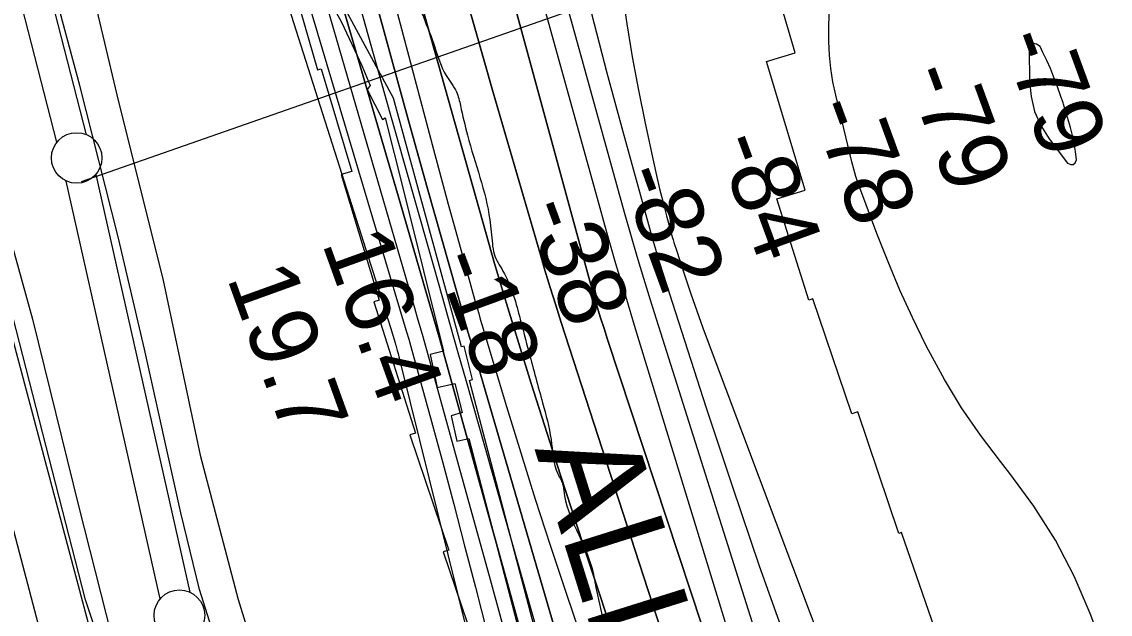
# Model space of a CAD drawing. Extents: x 3405885 to 3443815, y 558517 to 583997.
# Drawn here: x 3413539 to 3414615, y 576541 to 577127 of the extents above; entities that cross this region are included whole.
import ezdxf

# ---------------------------------------------------------------- set-up
doc = ezdxf.new("R2010")
doc.units = 0
for name, color, linetype in [('V-CHAN-DOCK', 7, 'Continuous'), ('V-FLOD-BASE', 7, 'Continuous'), ('V-LEVE-TOET', 7, 'Continuous'), ('V-RIVR-EDGE', 7, 'Continuous'), ('V-RIVR-RANG', 7, 'Continuous'), ('V-ROAD-CNTR', 7, 'Continuous'), ('V-RRAP-RVMT', 7, 'Continuous'), ('V-RRAP-RVMT-IDEN', 7, 'Continuous'), ('V-SURV-LINE', 7, 'Continuous'), ('V-TOPO-DPTH', 7, 'Continuous'), ('V-TOPO-MAJR', 7, 'Continuous'), ('V-TOPO-MINR', 7, 'Continuous'), ('V-TOPO-SHOR', 7, 'Continuous'), ('V-TOPO-WATR', 7, 'Continuous')]:
    doc.layers.add(name, color=color, linetype=linetype)

msp = doc.modelspace()

# ---------------------------------------------------------------- linework, layer by layer
at = {"layer": 'V-CHAN-DOCK'}
for points in [[(3414098.9, 576327.5), (3413981.9, 576772.3), (3413984.8, 576773), (3413976.8, 576806), (3413974, 576805.3), (3413906.9, 577051.1), (3413848.5, 577159.2), (3413854, 577160.6), (3413844.4, 577189.7), (3413841.9, 577189), (3413800.6, 577346.9), (3413804.2, 577347.4), (3413685.9, 577792.6)], [(3413838.8, 577156.7), (3413855.3, 577126.4), (3413875.6, 577083.4), (3413883.9, 577063.6), (3413880.8, 577059.8), (3413896, 577030.1), (3413898.5, 577031.6), (3413916.7, 576960), (3413956.3, 576801.1), (3413943, 576798), (3413949.9, 576765.4), (3413967.5, 576769.2), (3413974.8, 576740.5), (3413963.7, 576737.1), (3413969.5, 576712.1), (3413981.3, 576714.8), (3414038.7, 576494.8)]]:
    msp.add_lwpolyline(points, dxfattribs=at)
at = {"layer": 'V-FLOD-BASE'}
msp.add_lwpolyline([(3413966.8, 575593.2), (3413930, 575533.2), (3413867.4, 575424.5), (3413866.3, 575435.7), (3413891.6, 575528.1), (3413926.7, 575661.7), (3413958.1, 575773.5), (3413962.9, 575792.9), (3413964.2, 575799.4), (3413964.2, 575804.7), (3413956.2, 575840.2), (3413920.9, 575949.5), (3413875.3, 576086.5), (3413833.1, 576215.9), (3413788.5, 576347.1), (3413730.7, 576515.5), (3413715.1, 576565.7), (3413696.7, 576641.3), (3413660.7, 576803.1), (3413634.6, 576914.3), (3413596.7, 577063.8), (3413554.1, 577222), (3413512.2, 577391.5)], dxfattribs=at)
at = {"layer": 'V-LEVE-TOET'}
for points in [[(3413499, 577627.3), (3413496.6, 577619.1), (3413497.1, 577610.8), (3413502.2, 577577.8), (3413521.1, 577498.1), (3413563.2, 577351), (3413591.9, 577229.9), (3413633.2, 577054.6), (3413679.1, 576870.9), (3413715.7, 576698.5), (3413753.1, 576555.6), (3413784.9, 576453.4), (3413834.6, 576306.2), (3413880.9, 576173.3), (3413933, 576029.7), (3413974, 575893.8), (3413991.8, 575823.5), (3413994.1, 575811.1), (3413994, 575804.1), (3413975.8, 575718.7), (3413949.8, 575619.2)], [(3413389.6, 577437), (3413421.5, 577317.7), (3413459.4, 577170.7), (3413495.1, 577029.5), (3413549.8, 576832.8), (3413595.7, 576646.8), (3413644.6, 576454.9), (3413682.6, 576319.6), (3413700.5, 576256.6)]]:
    msp.add_lwpolyline(points, dxfattribs=at)
at = {"layer": 'V-RIVR-EDGE'}
msp.add_spline([(3412820.9, 582098.3), (3412817.8, 582058), (3412815.6, 582029.5), (3412817.7, 582007.9), (3412825.7, 581980.1), (3412850.3, 581879.9), (3412863.7, 581832.7), (3412872, 581799.1), (3412892.3, 581722.3), (3412903.2, 581678.4), (3412909.6, 581634.8), (3412920.5, 581599), (3412934, 581569.3), (3412943.4, 581548.5), (3412954.7, 581511.2), (3412955.3, 581484.9), (3412959.7, 581464), (3412965.1, 581459.6), (3412977.9, 581445), (3412992.4, 581409.1), (3413006.5, 581353.1), (3413015.2, 581302.3), (3413018.7, 581260.3), (3413013.9, 581236.1), (3413008.8, 581220.1), (3413005.1, 581206.5), (3413003.6, 581194.5), (3413004.7, 581180.2), (3413009.3, 581149.1), (3413020.6, 581117.3), (3413042, 581073), (3413073, 581031.3), (3413081, 581018.1), (3413088.7, 580999.8), (3413094.4, 580977.9), (3413100.2, 580939.1), (3413102.7, 580912), (3413106.3, 580894.1), (3413113.5, 580861.9), (3413124.8, 580824.3), (3413140, 580781.4), (3413146.5, 580756.9), (3413148.7, 580740.1), (3413153.8, 580721.8), (3413161, 580692.6), (3413184.2, 580615.7), (3413194, 580582.5), (3413204.2, 580568.2), (3413207.8, 580561.6), (3413214, 580535.3), (3413232.1, 580461.7), (3413244, 580397.7), (3413253, 580345.1), (3413251.9, 580330.8), (3413256.4, 580258.4), (3413262.5, 580217.5), (3413264.6, 580175.4), (3413271.5, 580146.5), (3413278.7, 580117.3), (3413280.2, 580104.8), (3413276.4, 580060.6), (3413276.3, 580025.9), (3413275.6, 580012.4), (3413275.5, 580006.1), (3413277.7, 580003.2), (3413288, 580000.6), (3413298.6, 579998.4), (3413303.7, 579992.2), (3413305.5, 579985.2), (3413310.1, 579953.8), (3413314.5, 579931.1), (3413321, 579914.6), (3413327.2, 579894.5), (3413327.1, 579868.9), (3413323.4, 579842.6), (3413317.9, 579835.3), (3413316, 579824.7), (3413315.6, 579806.5), (3413320, 579780.1), (3413328, 579765.1), (3413335.6, 579758.2), (3413338.2, 579753.4), (3413338.9, 579747.5), (3413338.9, 579742.8), (3413335.5, 579730.7), (3413330.8, 579723.1), (3413327.8, 579714.3), (3413325.2, 579701.2), (3413326.7, 579689.5), (3413332.1, 579675.9), (3413338.3, 579668.2), (3413342.7, 579666.4), (3413352.6, 579666.7), (3413357.3, 579663.4), (3413365.3, 579652.4), (3413371.9, 579635.2), (3413374.8, 579618.4), (3413377.6, 579592.5), (3413379.4, 579557.4), (3413373.8, 579521.6), (3413375.2, 579501.1), (3413382.1, 579476.9), (3413395.1, 579440), (3413408.6, 579400.8), (3413417.6, 579358.8), (3413445.2, 579297.7), (3413449.9, 579271.7), (3413449.8, 579233.3), (3413439.5, 579191.3), (3413438.7, 579182.2), (3413439.8, 579172.7), (3413446, 579161.7), (3413464.9, 579134.6), (3413487.5, 579101.6), (3413497, 579074.9), (3413502.7, 579046.4), (3413506.7, 579018.2), (3413510.6, 578990.8), (3413518.6, 578952.4), (3413529.8, 578903.8), (3413538.1, 578871.6), (3413547.9, 578834.6), (3413558.4, 578787.4), (3413566.7, 578743.2), (3413574.6, 578699.3), (3413585.1, 578637.1), (3413595.2, 578577.2), (3413599.5, 578547.5), (3413610.7, 578516.1), (3413620.2, 578504), (3413626, 578499.2), (3413635.5, 578497), (3413635.9, 578494.4), (3413634.1, 578490.1), (3413632.2, 578487.1), (3413632.2, 578479.5), (3413633.2, 578455), (3413642.2, 578391), (3413644.3, 578359.2), (3413649, 578338.7), (3413656.3, 578322.2), (3413667.6, 578313.8), (3413676, 578309), (3413684.4, 578305.3), (3413688.8, 578300.2), (3413697.9, 578288.5), (3413702.2, 578272.4), (3413709.1, 578250.8), (3413714.9, 578233.2), (3413728.7, 578187.2), (3413734.8, 578151.3), (3413738.8, 578114.4), (3413740.5, 578084), (3413746.7, 578059.2), (3413750.7, 578043.4), (3413751.3, 578020), (3413747.6, 577990.8), (3413742, 577955), (3413736.9, 577934.5), (3413735.4, 577919.6), (3413733.5, 577904.2), (3413737.1, 577880.1), (3413741.4, 577864.7), (3413741.4, 577863.2), (3413750.2, 577865.8), (3413755, 577862.8), (3413760, 577845.7), (3413773.8, 577798.1), (3413781.8, 577765.2), (3413793, 577724.9), (3413797, 577700.4), (3413803.4, 577637.2), (3413804.4, 577613.8), (3413807.7, 577591.8), (3413815.3, 577561.1), (3413829.4, 577524.9), (3413841.8, 577493.8), (3413853.8, 577466), (3413863.2, 577445.5), (3413869.8, 577431.2), (3413869.8, 577426.1), (3413869.7, 577412.9), (3413868.9, 577389.5), (3413869.2, 577353), (3413871, 577339.8), (3413873.9, 577328.5), (3413883, 577306.5), (3413889.5, 577287.9), (3413905.1, 577244.3), (3413913.5, 577211), (3413925.4, 577161.3), (3413947.6, 577101.7), (3413958.8, 577073.5), (3413969, 577057.4), (3413973, 577043.8), (3413979.9, 577014.6), (3414002, 576930.8), (3414004.5, 576907.4), (3414006.3, 576897.2), (3414015, 576880.3), (3414024.5, 576858.8), (3414031.3, 576835.7), (3414040.8, 576799.5), (3414054.2, 576750.1), (3414062.5, 576713.9), (3414069.3, 576679.9), (3414074.4, 576668.5), (3414075.1, 576663.4), (3414103.1, 576586.2), (3414107.4, 576564.6), (3414115.4, 576529.2), (3414119, 576508), (3414142.2, 576433.7), (3414153.5, 576399.3), (3414159.6, 576378.5), (3414164.7, 576348.8), (3414174.1, 576303.8), (3414178, 576275), (3414184.1, 576248.3), (3414191.1, 576234), (3414204.1, 576202.1), (3414212.1, 576179.5), (3414243, 576089.5), (3414264.8, 576025.4), (3414269.5, 576005.7), (3414269.4, 575994.4), (3414267.6, 575989.1)], degree=3, dxfattribs=at)
at = {"layer": 'V-RIVR-RANG'}
msp.add_line((3413598.5, 576968.9), (3414485.8, 577279.2), dxfattribs=at)
at = {"layer": 'V-ROAD-CNTR'}
msp.add_lwpolyline([(3412427.1, 581014.8), (3412474.8, 580838.1), (3412987, 578854.7), (3413723.7, 576086.7)], dxfattribs=at)
at = {"layer": 'V-RRAP-RVMT'}
for points in [[(3414453.7, 576492.6), (3414409.1, 576621.8), (3414406.4, 576620.8), (3414365.7, 576741.2), (3414359.7, 576739.2), (3414321.2, 576853), (3414317.2, 576851.7), (3414285.6, 576951.7), (3414313.7, 576960.2), (3414275.4, 577087.5), (3414304, 577096), (3414271.4, 577206.1), (3414281.9, 577209.2), (3414243, 577344.3), (3414262.9, 577350.2), (3414224.5, 577479.4), (3414222.9, 577478.9), (3414188.7, 577597.3), (3414195.6, 577599.4), (3414154.2, 577736.4)], [(3413652.8, 577721.4), (3413690, 577595.9), (3413688.2, 577595.4), (3413725.6, 577471.8), (3413722.8, 577471), (3413763.6, 577330.1), (3413764, 577330.2), (3413793.3, 577231.6), (3413788.3, 577230.2), (3413831.8, 577079.3), (3413835.3, 577080.3), (3413865.5, 576978.7), (3413855.2, 576975.6), (3413892.6, 576851.5), (3413887.4, 576849.9), (3413928.5, 576720.2), (3413923, 576718.4), (3413961.4, 576604.5), (3413956, 576602.7), (3413997.6, 576479.5)]]:
    msp.add_lwpolyline(points, dxfattribs=at)
at = {"layer": 'V-SURV-LINE'}
for points in [[(3413574.1, 577007.7), (3412835.6, 579881.8)], [(3412864.6, 579889.2), (3413603.1, 577015.1)], [(3413612.6, 576975.9), (3413705.5, 576562.9)], [(3413676.2, 576556.3), (3413583.3, 576969.3)]]:
    msp.add_lwpolyline(points, dxfattribs=at)
for centre in [(3413593.6, 576992.1), (3413695.2, 576540.1)]:
    msp.add_circle(centre, 25, dxfattribs=at)
at = {"layer": 'V-TOPO-DPTH'}
for points in [[(3413870.4, 577720.3), (3413910.7, 577570.7), (3413931, 577495.3), (3413951.4, 577420), (3413971.8, 577344.6), (3413992.3, 577269.3), (3414092.8, 576899.2), (3414095.8, 576888.3), (3414098.8, 576877.5), (3414101.9, 576866.6), (3414105, 576855.8), (3414108.2, 576844.9), (3414111.5, 576834.2), (3414114.9, 576823.4), (3414118.4, 576812.7), (3414340.3, 576140.2), (3414345.1, 576125.9), (3414350, 576111.6), (3414355.1, 576097.4), (3414360.2, 576083.2), (3414623.5, 575371.4)], [(3413870.4, 577720.3), (3413910.7, 577570.7), (3413931, 577495.3), (3413951.4, 577420), (3413971.8, 577344.6), (3413992.3, 577269.3), (3414092.8, 576899.2), (3414095.8, 576888.3), (3414098.8, 576877.5), (3414101.9, 576866.6), (3414105, 576855.8), (3414108.2, 576844.9), (3414111.5, 576834.2), (3414114.9, 576823.4), (3414118.4, 576812.7), (3414340.3, 576140.2), (3414345.1, 576125.9), (3414350, 576111.6), (3414355.1, 576097.4), (3414360.2, 576083.2), (3414623.5, 575371.4)], [(3414176.3, 576509.8), (3414149.5, 576591.8), (3414072.6, 576829.5), (3414067.2, 576846.7), (3414061.8, 576864), (3414056.5, 576881.3), (3414051.4, 576898.6), (3414005.4, 577056.7), (3413978, 577153.3), (3413951.2, 577250), (3413925.5, 577347), (3413900.6, 577444.3), (3413843.2, 577673.7)], [(3414176.3, 576509.8), (3414149.5, 576591.8), (3414072.6, 576829.5), (3414067.2, 576846.7), (3414061.8, 576864), (3414056.5, 576881.3), (3414051.4, 576898.6), (3414005.4, 577056.7), (3413978, 577153.3), (3413951.2, 577250), (3413925.5, 577347), (3413900.6, 577444.3), (3413843.2, 577673.7)], [(3413754, 577659.2), (3413869.2, 577223.1), (3413886.5, 577157.9), (3413904.1, 577092.8), (3413922, 577027.8), (3413940.2, 576962.9), (3413969.6, 576858.5), (3413973.2, 576845.8), (3413976.8, 576833.1), (3413980.4, 576820.4), (3413984.1, 576807.7), (3414083.7, 576466.7)], [(3414083.7, 576466.7), (3413984.1, 576807.7), (3413980.4, 576820.4), (3413976.8, 576833.1), (3413973.2, 576845.8), (3413969.6, 576858.5), (3413940.2, 576962.9), (3413922, 577027.8), (3413904.1, 577092.8), (3413886.5, 577157.9), (3413869.2, 577223.1), (3413754, 577659.2)], [(3413669.5, 577652.8), (3413721.3, 577482.2), (3413749, 577390.6), (3413776.6, 577299), (3413804.2, 577207.3), (3413831.6, 577115.6), (3413917.5, 576827.7), (3413919.7, 576820.4), (3413921.8, 576813.1), (3413923.9, 576805.8), (3413925.9, 576798.4), (3413944.3, 576731.5), (3413955.5, 576690.7), (3413966.4, 576649.8), (3413977.1, 576608.8), (3413987.7, 576567.8), (3414103.6, 576111.6)], [(3413718.9, 577631.5), (3413770.4, 577445.8), (3413839.6, 577200.4), (3413913, 576949), (3413952.7, 576812.7), (3414019.4, 576571.6), (3414062.4, 576415.7), (3414113.9, 576220.6), (3414156.9, 576063), (3414193.2, 575932.6), (3414227.8, 575803.1), (3414306.3, 575543.2), (3414400.9, 575243.3), (3414476.2, 575016.6), (3414482.1, 574999.6), (3414486.3, 574987.7), (3414536.2, 574860.7), (3414616.6, 574655.3)], [(3414616.6, 574655.3), (3414536.2, 574860.7), (3414486.3, 574987.7), (3414482.1, 574999.6), (3414476.2, 575016.6), (3414400.9, 575243.3), (3414306.3, 575543.2), (3414227.8, 575803.1), (3414193.2, 575932.6), (3414156.9, 576063), (3414113.9, 576220.6), (3414062.4, 576415.7), (3414019.4, 576571.6), (3413952.7, 576812.7), (3413913, 576949), (3413839.6, 577200.4), (3413770.4, 577445.8), (3413718.9, 577631.5)], [(3414626.9, 575077.5), (3414533.7, 575346.5), (3414490.7, 575470.4), (3414447.6, 575594.3), (3414404.3, 575718.2), (3414360.9, 575841.9), (3414304.1, 576003.7), (3414289, 576046.6), (3414273.9, 576089.5), (3414258.9, 576132.3), (3414243.8, 576175.2), (3414185.4, 576341.3), (3414156.2, 576425.3), (3414127.5, 576509.5), (3414099.5, 576594), (3414072, 576678.6), (3414043, 576769.2), (3414030.6, 576808.6), (3414018.4, 576848.2), (3414006.7, 576887.9), (3413995.3, 576927.6), (3413796.5, 577634.1)], [(3413796.5, 577634.1), (3413995.3, 576927.6), (3414006.7, 576887.9), (3414018.4, 576848.2), (3414030.6, 576808.6), (3414043, 576769.2), (3414072, 576678.6), (3414099.5, 576594), (3414127.5, 576509.5), (3414156.2, 576425.3), (3414185.4, 576341.3), (3414243.8, 576175.2), (3414258.9, 576132.3), (3414273.9, 576089.5), (3414289, 576046.6), (3414304.1, 576003.7), (3414360.9, 575841.9), (3414404.3, 575718.2), (3414447.6, 575594.3), (3414490.7, 575470.4), (3414533.7, 575346.5), (3414626.9, 575077.5)]]:
    msp.add_lwpolyline(points, dxfattribs=at)
at = {"layer": 'V-TOPO-MAJR'}
msp.add_lwpolyline([(3414242.8, 576506.9), (3414146, 576823.2), (3414136.3, 576855.4), (3414126.7, 576887.6), (3414117.5, 576919.9), (3414108.3, 576952.2), (3413980.9, 577411.4), (3413966.4, 577464.2), (3413952.1, 577517), (3413938.1, 577569.9), (3413924.2, 577622.8), (3413903.4, 577703.2)], dxfattribs=at)
at = {"layer": 'V-TOPO-MINR'}
for points in [[(3414623.5, 575371.4), (3414360.2, 576083.2), (3414355.1, 576097.4), (3414350, 576111.6), (3414345.1, 576125.9), (3414340.3, 576140.2), (3414118.4, 576812.7), (3414114.9, 576823.4), (3414111.5, 576834.2), (3414108.2, 576844.9), (3414105, 576855.8), (3414101.9, 576866.6), (3414098.8, 576877.5), (3414095.8, 576888.3), (3414092.8, 576899.2), (3413992.3, 577269.3), (3413971.8, 577344.6), (3413951.4, 577420), (3413931, 577495.3), (3413910.7, 577570.7), (3413870.4, 577720.3)], [(3413766.1, 577680.1), (3413946.4, 577000.4), (3413953.7, 576973.3), (3413961, 576946.3), (3413968.4, 576919.3), (3413975.9, 576892.2), (3413988, 576849), (3413989.5, 576843.7), (3413991.1, 576838.3), (3413992.6, 576832.9), (3413994.2, 576827.5), (3414018.5, 576746.5), (3414032.6, 576700.7), (3414046.9, 576655), (3414061.7, 576609.5), (3414076.8, 576564.1), (3414222.6, 576132.9)], [(3413936.5, 577683.9), (3413976.2, 577527.7), (3414003, 577423.6), (3414030.3, 577319.6), (3414058.2, 577215.8), (3414086.7, 577112.1), (3414134.8, 576938.6), (3414141, 576916.8), (3414147.3, 576895.1), (3414153.9, 576873.4), (3414160.6, 576851.8), (3414309.9, 576379.8), (3414323.7, 576337.1), (3414338, 576294.6), (3414352.7, 576252.2), (3414367.9, 576210), (3414371.6, 576200), (3414385.5, 576163), (3414399.7, 576126.1), (3414414.4, 576089.5), (3414429.4, 576052.9), (3414787.8, 575198.5)], [(3413843.2, 577673.7), (3413900.6, 577444.3), (3413925.5, 577347), (3413951.2, 577250), (3413978, 577153.3), (3414005.4, 577056.7), (3414051.4, 576898.6), (3414056.5, 576881.3), (3414061.8, 576864), (3414067.2, 576846.7), (3414072.6, 576829.5), (3414149.5, 576591.8), (3414176.3, 576509.8)], [(3413754, 577659.2), (3413869.2, 577223.1), (3413886.5, 577157.9), (3413904.1, 577092.8), (3413922, 577027.8), (3413940.2, 576962.9), (3413969.6, 576858.5), (3413973.2, 576845.8), (3413976.8, 576833.1), (3413980.4, 576820.4), (3413984.1, 576807.7), (3414083.7, 576466.7)], [(3413974.3, 577661.1), (3414073.2, 577251.9), (3414087.7, 577193.3), (3414102.5, 577134.8), (3414117.8, 577076.4), (3414133.5, 577018.1), (3414158.7, 576926.4), (3414162.2, 576914.1), (3414165.7, 576901.8), (3414169.5, 576889.6), (3414173.3, 576877.4), (3414216, 576745.1), (3414241.8, 576667), (3414268.4, 576589.1), (3414296, 576511.6), (3414324.3, 576434.3), (3414421.5, 576174.6), (3414428.7, 576155.6), (3414436.1, 576136.7), (3414443.6, 576117.8), (3414451.2, 576099), (3414563.2, 575827), (3414608.9, 575716.2), (3414654.8, 575605.5)], [(3413669.5, 577652.8), (3413721.3, 577482.2), (3413749, 577390.6), (3413776.6, 577299), (3413804.2, 577207.3), (3413831.6, 577115.6), (3413917.5, 576827.7), (3413919.7, 576820.4), (3413921.8, 576813.1), (3413923.9, 576805.8), (3413925.9, 576798.4), (3413944.3, 576731.5), (3413955.5, 576690.7), (3413966.4, 576649.8), (3413977.1, 576608.8), (3413987.7, 576567.8), (3414103.6, 576111.6)], [(3413644.9, 577638.2), (3413651, 577618.4), (3413893.6, 576857), (3413896.2, 576848.9), (3413898.7, 576840.8), (3413901.2, 576832.7), (3413903.7, 576824.6), (3413908.3, 576809.5), (3413908.9, 576807.7), (3413909, 576807.2), (3413910.4, 576801.9), (3413911.3, 576798.7), (3413912.2, 576795.5), (3413913, 576792.3), (3413913.8, 576789.1), (3414091.8, 576071)], [(3413740.9, 577636.5), (3413788.5, 577455.6), (3413816.5, 577350.7), (3413844.8, 577245.9), (3413873.8, 577141.3), (3413903.2, 577036.8), (3413946.6, 576884.2), (3413954.6, 576856.1), (3413962.5, 576827.9), (3413970.5, 576799.8), (3413978.5, 576771.6), (3414144, 576188.2)], [(3413796.5, 577634.1), (3413995.3, 576927.6), (3414006.7, 576887.9), (3414018.4, 576848.2), (3414030.6, 576808.6), (3414043, 576769.2), (3414072, 576678.6), (3414099.5, 576594), (3414127.5, 576509.5), (3414156.2, 576425.3), (3414185.4, 576341.3), (3414243.8, 576175.2), (3414258.9, 576132.3), (3414273.9, 576089.5), (3414289, 576046.6), (3414304.1, 576003.7), (3414360.9, 575841.9), (3414404.3, 575718.2), (3414447.6, 575594.3), (3414490.7, 575470.4), (3414533.7, 575346.5), (3414626.9, 575077.5)], [(3413702.2, 577623.3), (3413708.8, 577599.1), (3413715.5, 577574.8), (3413722.3, 577550.7), (3413729.2, 577526.5), (3413926.9, 576846.2), (3413931, 576832.1), (3413935.1, 576817.9), (3413939.1, 576803.8), (3413943, 576789.7), (3413980.1, 576656.3), (3414002.4, 576575.5), (3414024.4, 576494.6)], [(3414132.4, 577157.7), (3414137.3, 577124.8), (3414142.7, 577091.9), (3414148.9, 577059.2), (3414155.5, 577026.5), (3414163.7, 576988.2), (3414166.7, 576974.8), (3414169.9, 576961.5), (3414173.2, 576948.2), (3414176.7, 576934.9), (3414182.4, 576914.1), (3414183.2, 576911.3), (3414184, 576908.5), (3414184.9, 576905.7), (3414185.8, 576902.9), (3414195.1, 576874.6), (3414200.7, 576857.8), (3414206.5, 576841), (3414212.5, 576824.2), (3414218.7, 576807.5), (3414464.9, 576152.8)], [(3414701.4, 576262.4), (3414595.6, 576541.8), (3414579.6, 576578.6), (3414561.3, 576614.2), (3414539.8, 576647.9), (3414516.1, 576680.4), (3414506.8, 576692), (3414486.9, 576718.2), (3414468.3, 576745.2), (3414451.3, 576773.3), (3414435.6, 576802.1), (3414433, 576807.2), (3414419.8, 576834.3), (3414407.3, 576861.6), (3414395.7, 576889.3), (3414384.6, 576917.3), (3414368.7, 576959.8), (3414366.2, 576966.8), (3414363.9, 576973.8), (3414361.8, 576981), (3414359.9, 576988.2), (3414343.9, 577054.2), (3414341.1, 577067.3), (3414339, 577080.5), (3414337.7, 577093.8), (3414337, 577107.2), (3414337, 577120.7), (3414337.5, 577134.1)], [(3414556.1, 577080.6), (3414552.5, 577088.5), (3414548.8, 577096.4), (3414545.9, 577102.2), (3414542.5, 577104.5), (3414539.6, 577105.1), (3414537.3, 577103.3), (3414535.3, 577099.7), (3414535.5, 577068), (3414537.1, 577052.7), (3414540.5, 577038), (3414546.7, 577024.2), (3414554.9, 577011.1), (3414573.2, 576987.1), (3414576.2, 576985.7), (3414578.7, 576985.5), (3414580.5, 576987.3), (3414581.8, 576990.4), (3414580.9, 576998.4), (3414579.7, 577006.4), (3414578, 577014.3), (3414575.9, 577022.2), (3414569.1, 577045.3), (3414568.7, 577046.7), (3414567.7, 577049.6), (3414567.2, 577051), (3414562.4, 577064.5), (3414559.3, 577072.6), (3414556.1, 577080.6)]]:
    msp.add_lwpolyline(points, dxfattribs=at)
at = {"layer": 'V-TOPO-SHOR'}
for points in [[(3413698.6, 576266.4), (3413602.5, 576555.5), (3413510.9, 576911.1), (3413385.6, 577404.2)], [(3413416.8, 577054.8), (3413475, 576835.8), (3413563.9, 576499.6), (3413596.4, 576365.1)]]:
    msp.add_lwpolyline(points, dxfattribs=at)
at = {"layer": 'V-TOPO-WATR'}
msp.add_lwpolyline([(3414616.6, 574655.3), (3414536.2, 574860.7), (3414486.3, 574987.7), (3414482.1, 574999.6), (3414476.2, 575016.6), (3414400.9, 575243.3), (3414306.3, 575543.2), (3414227.8, 575803.1), (3414193.2, 575932.6), (3414156.9, 576063), (3414113.9, 576220.6), (3414062.4, 576415.7), (3414019.4, 576571.6), (3413952.7, 576812.7), (3413913, 576949), (3413839.6, 577200.4), (3413770.4, 577445.8), (3413718.9, 577631.5)], dxfattribs=at)

# ---------------------------------------------------------------- texts
at = {"layer": 'V-RIVR-RANG'}
for s, rotation, p in [('-79', 290.1248, (3414506.9, 577109.4)), ('-79', 290.1248, (3414412.9, 577075.2)), ('-78', 290.1248, (3414318.7, 577041.8)), ('-84', 290.1248, (3414224.8, 577007.4)), ('-82', 290.1248, (3414129.8, 576975.9)), ('-38', 290.1248, (3414035.6, 576942.3)), ('16.4', 289.8383, (3413835.7, 576908.2)), ('-18', 290.1248, (3413947.7, 576891.7)), ('19.7', 289.8383, (3413741.8, 576874))]:
    msp.add_text(s, height=67, rotation=rotation, dxfattribs=at).set_placement(p)
at = {"layer": 'V-RRAP-RVMT-IDEN'}
msp.add_text('ALICE', height=100, rotation=287.418, dxfattribs=at).set_placement((3414046.1, 576704.4))

doc.saveas('drawing.dxf')
